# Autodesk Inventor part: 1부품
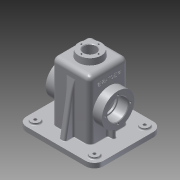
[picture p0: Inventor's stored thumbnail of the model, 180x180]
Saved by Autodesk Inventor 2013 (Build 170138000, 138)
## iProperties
Created: 2016-01
Part Number: 1부품
Material: 알루미늄 6061
Document SubType Name: Modeling
Designer: Administrator
Density: 2.71 g/cm^3
Mass: 808.405 g
Surface Area: 920.161 cm^2
Volume: 298.305 cm^3
Author: Administrator
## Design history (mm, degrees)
sketch "스케치1"
  geometry: L1 (-65, 57.5)-(65, 57.5); L2 (65, 57.5)-(65, -57.5); L3 (65, -57.5)-(-65, -57.5); L4 (-65, -57.5)-(-65, 57.5); L5 (-65, 57.5)-(65, -57.5); L6 (65, 57.5)-(-65, -57.5); 1 further point
  constraints: 12 end point, 2 midpoint, 2 parallel, 1 horizontal, 1 perpendicular
  dimensions: "d0" = 130 distance of L2.end L3.end; "d2" = 115 distance of L1.end L2.end
extrude "돌출1" new body sketch "스케치1" distance "d3" = 10; taper "d4" = 0 deg
fillet "모깎기1" dims "d5" = 15
sketch "스케치2"
  geometry: L1 (-32.5, 32.5)-(32.5, 32.5); L2 (32.5, 32.5)-(32.5, -32.5); L3 (32.5, -32.5)-(-32.5, -32.5); L4 (-32.5, -32.5)-(-32.5, 32.5); L5 (-32.5, 32.5)-(32.5, -32.5); L6 (32.5, 32.5)-(-32.5, -32.5); 1 further point
  constraints: 12 end point, 2 midpoint, 2 parallel, 1 horizontal, 1 perpendicular
  dimensions: "d6" = 65 distance of L1.start L1.end; "d8" = 65 distance of L1.end L2.end
extrude "돌출2" join sketch "스케치2" distance "d9" = 100; taper "d10" = 0 deg
fillet "모깎기2" dims "d11" = 8
sketch "스케치3"
  geometry: L1 (65, -42.5)-(65, 42.5) reference; L2 (50, 57.5)-(-50, 57.5) reference; L3 (-65, 42.5)-(-65, -42.5) reference; L4 (-50, -57.5)-(50, -57.5) reference; L5 (-50, -52.5)-(50, -52.5); L6 (60, -42.5)-(60, 42.5); L7 (50, 52.5)-(-50, 52.5); L8 (-60, 42.5)-(-60, -42.5); L9 (-60, -52.5)-(60, 52.5); L10 (60, -52.5)-(-60, 52.5); A1 r 15 centre (50, -42.5) between (50, -57.5) and (65, -42.5) reference; A2 r 15 centre (50, 42.5) between (65, 42.5) and (50, 57.5) reference; A3 r 15 centre (-50, 42.5) between (-50, 57.5) and (-65, 42.5) reference; A4 r 15 centre (-50, -42.5) between (-65, -42.5) and (-50, -57.5) reference; A5 r 10 centre (-50, -42.5) between (-60, -42.5) and (-50, -52.5); A6 r 10 centre (50, -42.5) between (50, -52.5) and (60, -42.5); A7 r 10 centre (50, 42.5) between (60, 42.5) and (50, 52.5); A8 r 10 centre (-50, 42.5) between (-50, 52.5) and (-60, 42.5); 1 further point
  constraints: 12 end point, 8 point on circle, 8 point on line, 8 tangent, 4 centre point, 3 equal radius, 2 midpoint, 2 parallel, 1 horizontal, 1 perpendicular
  dimensions: "d13" = 120 distance of L9.end L10.end; "d15" = 105 distance of L10.end L9.start; "d16" = 10 radius of A5
extrude "돌출3" cut sketch "스케치3" distance "d17" = 2; taper "d18" = 0 deg
sketch "스케치4"
  geometry: L1 (-24.5, -27.5)-(24.5, -27.5); L2 (27.5, -24.5)-(27.5, 24.5); L3 (24.5, 27.5)-(-24.5, 27.5); L4 (-27.5, 24.5)-(-27.5, -24.5); L5 (-27.5, -27.5)-(27.5, 27.5); L6 (27.5, -27.5)-(-27.5, 27.5); A1 r 3 centre (-24.5, -24.5) between (-27.5, -24.5) and (-24.5, -27.5); A2 r 3 centre (24.5, -24.5) between (24.5, -27.5) and (27.5, -24.5); A3 r 3 centre (24.5, 24.5) between (27.5, 24.5) and (24.5, 27.5); A4 r 3 centre (-24.5, 24.5) between (-24.5, 27.5) and (-27.5, 24.5); 1 further point
  constraints: 12 end point, 8 point on circle, 8 point on line, 8 tangent, 4 centre point, 3 equal radius, 2 midpoint, 2 parallel, 1 horizontal, 1 perpendicular
  dimensions: "d19" = 55 distance of L6.end L5.start; "d21" = 55 distance of L5.end L6.end; "d22" = 3 radius of A1
extrude "돌출4" cut sketch "스케치4" distance "d23" = 105; taper "d24" = 0 deg
fillet "모깎기3" dims "d25" = 3
sketch "스케치5"
  geometry: C1 r 20 at (0, 0); 1 further point
  constraints: 1 centre point, 1 coincident
  dimensions: "d26" = 40 diameter of C1
extrude "돌출5" join sketch "스케치5" distance "d27" = 10; taper "d28" = 0 deg
hole "구멍1" diameter "d31" = 21; stored, may be unused: countersink angle "d35" = 90 deg, drill point angle "d37" = 118 deg; dims "d29" = 10, "d30" = 10, "d32" = 6, "d33" = 4, "d34" = 2, "d36" = 8
sketch "스케치6"
  geometry: C1 r 10.5 at (0, 0) reference; 1 further point
  constraints: 1 vertical alignment
  dimensions: "d38" = 14.5 distance of C1.centre point (0, 14.5)
hole "구멍2" sketch "스케치6" at (0, 14.5) diameter "d39" = 2.459; stored, may be unused: countersink angle "d43" = 90 deg, drill point angle "d45" = 118 deg; dims "d40" = 7, "d41" = 4, "d42" = 2, "d44" = 9
sketch "스케치7"
  geometry: L1 (-52.5, 0)-(-52.5, 2) reference; L2 (-52.5, 2)-(-57.5, 2) reference; L3 (-57.5, 2)-(-57.5, 10) reference; L4 (-57.5, 10)-(-32.5, 10) reference; L5 (-32.5, 10)-(-32.5, 110) reference; L6 (-32.5, 110)-(-20, 110) reference; L7 (-20, 110)-(-20, 120) reference; L8 (-20, 120)-(-15.73, 120) reference; L9 (-15.73, 120)-(-15.73, 111) reference; L10 (-15.73, 111)-(-14.5, 110.261) reference; L11 (-14.5, 110.261)-(-13.271, 111) reference; L12 (-13.271, 111)-(-13.271, 120) reference; L13 (-13.271, 120)-(-10.5, 120) reference; L14 (-10.5, 120)-(-10.5, 105) reference; L15 (-10.5, 105)-(-24.5, 105) reference; L16 (-27.5, 102)-(-27.5, 0) reference; L17 (-27.5, 0)-(-52.5, 0) reference; L18 (32.5, 110)-(32.5, 10) reference; L19 (32.5, 10)-(57.5, 10) reference; L20 (57.5, 10)-(57.5, 2) reference; L21 (57.5, 2)-(52.5, 2) reference; L22 (52.5, 2)-(52.5, 0) reference; L23 (52.5, 0)-(27.5, 0) reference; L24 (27.5, 0)-(27.5, 102) reference; L25 (24.5, 105)-(10.5, 105) reference; L26 (10.5, 105)-(10.5, 120) reference; L27 (10.5, 120)-(13.271, 120) reference; L28 (13.271, 120)-(13.271, 111) reference; L29 (13.271, 111)-(14.5, 110.261) reference; L30 (14.5, 110.261)-(15.73, 111) reference; L31 (15.73, 111)-(15.73, 120) reference; L32 (15.73, 120)-(20, 120) reference; L33 (20, 120)-(20, 110) reference; L34 (20, 110)-(32.5, 110) reference; C1 r 27.5 at (0, 55); A1 r 3 centre (-24.5, 102) between (-24.5, 105) and (-27.5, 102) reference; A2 r 3 centre (24.5, 102) between (27.5, 102) and (24.5, 105) reference; 1 further point
  constraints: 1 centre point, 1 vertical alignment
  dimensions: "d49" = 55 diameter of C1; "d50" = 55 distance of point (0, 0) C1.centre
extrude "돌출6" join sketch "스케치7" stored distance "d51" = 95; taper "d52" = 0 deg
hole "구멍3" diameter "d55" = 30; stored, may be unused: countersink angle "d59" = 90 deg, drill point angle "d61" = 0 deg; dims "d56" = 7, "d57" = 35, "d58" = 17, "d60" = 9, "d62" = 10, "d63" = 10
sketch "스케치8"
  geometry: C1 r 17.5 at (0, 0) reference; 2 further points
  constraints: 1 horizontal alignment
  dimensions: "d64" = 21 distance of C1.centre point (-21, 0)
hole "구멍4" sketch "스케치8" at (-21, 0) diameter "d65" = 3.242; stored, may be unused: countersink angle "d69" = 90 deg, drill point angle "d71" = 118 deg; dims "d66" = 8, "d67" = 42, "d68" = 17, "d70" = 10
sketch "스케치9"
  geometry: L1 (-20, 110)-(-20, 120) reference; L2 (-20, 120)-(-15.73, 120) reference; L3 (-15.73, 120)-(-15.73, 111) reference; L4 (-15.73, 111)-(-14.5, 110.261) reference; L5 (-14.5, 110.261)-(-13.271, 111) reference; L6 (-13.271, 111)-(-13.271, 120) reference; L7 (-13.271, 120)-(-10.5, 120) reference; L8 (-10.5, 120)-(-10.5, 105) reference; L9 (-10.5, 105)-(-24.5, 105) reference; L10 (-27.5, 102)-(-27.5, 82.5) reference; L11 (-27.5, 82.5)-(27.5, 82.5) reference; L12 (27.5, 82.5)-(27.5, 102) reference; L13 (24.5, 105)-(10.5, 105) reference; L14 (10.5, 105)-(10.5, 120) reference; L15 (10.5, 120)-(13.271, 120) reference; L16 (13.271, 120)-(13.271, 111) reference; L17 (13.271, 111)-(14.5, 110.261) reference; L18 (14.5, 110.261)-(15.73, 111) reference; L19 (15.73, 111)-(15.73, 120) reference; L20 (15.73, 120)-(20, 120) reference; L21 (20, 120)-(20, 110) reference; L22 (20, 110)-(32.5, 110) reference; L23 (32.5, 110)-(32.5, 82.5) reference; L24 (32.5, 82.5)-(47.5, 82.5) reference; L25 (47.5, 82.5)-(47.5, 77.621) reference; L26 (47.5, 77.621)-(37.5, 77.621) reference; L27 (37.5, 77.621)-(36.526, 76) reference; L28 (37.5, 74.379)-(47.5, 74.379) reference; L29 (47.5, 74.379)-(47.5, 72.5) reference; L30 (47.5, 72.5)-(30.5, 72.5) reference; L31 (30.5, 72.5)-(30.5, 70) reference; L32 (30.5, 70)-(-30.5, 70) reference; L33 (-30.5, 70)-(-30.5, 72.5) reference; L34 (-30.5, 72.5)-(-47.5, 72.5) reference; L35 (-47.5, 72.5)-(-47.5, 74.379) reference; L36 (-47.5, 74.379)-(-37.5, 74.379) reference; L37 (-37.5, 74.379)-(-36.526, 76) reference; L38 (-37.5, 77.621)-(-47.5, 77.621) reference; L39 (-47.5, 77.621)-(-47.5, 82.5) reference; L40 (-47.5, 82.5)-(-32.5, 82.5) reference; L41 (-32.5, 82.5)-(-32.5, 110) reference; L42 (-32.5, 110)-(-20, 110) reference; L43 (-60, 0)-(-60, 2) reference; L44 (-60, 2)-(-65, 2) reference; L45 (-65, 2)-(-65, 10) reference; L46 (-65, 10)-(-32.5, 10) reference; L47 (-32.5, 10)-(-32.5, 27.5) reference; L48 (-32.5, 27.5)-(-47.5, 27.5) reference; L49 (-47.5, 27.5)-(-47.5, 32.379) reference; L50 (-47.5, 32.379)-(-37.5, 32.379) reference; L51 (-37.5, 32.379)-(-36.526, 34) reference; L52 (-37.5, 35.621)-(-47.5, 35.621) reference; L53 (-47.5, 35.621)-(-47.5, 37.5) reference; L54 (-47.5, 37.5)-(-30.5, 37.5) reference; L55 (-30.5, 37.5)-(-30.5, 40) reference; L56 (-30.5, 40)-(30.5, 40) reference; L57 (30.5, 40)-(30.5, 37.5) reference; L58 (30.5, 37.5)-(47.5, 37.5) reference; L59 (47.5, 37.5)-(47.5, 35.621) reference; L60 (47.5, 35.621)-(37.5, 35.621) reference; L61 (37.5, 35.621)-(36.526, 34) reference; L62 (37.5, 32.379)-(47.5, 32.379) reference; L63 (47.5, 32.379)-(47.5, 27.5) reference; L64 (47.5, 27.5)-(32.5, 27.5) reference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; A1 r 3 centre (-24.5, 102) between (-24.5, 105) and (-27.5, 102) reference; A2 r 3 centre (24.5, 102) between (27.5, 102) and (24.5, 105) reference; 1 further point
  constraints: 4 end point, 4 point on line, 2 perpendicular, 1 parallel
  dimensions: "d75" = 15 distance between parallel lines of L75 L71; "d76" = 15 distance between parallel lines of L76 L73
extrude "돌출7" join sketch "스케치9" stored distance "d77" = 6; taper "d78" = 0 deg
sketch "스케치10"
  geometry: L1 (-52.5, 0)-(-52.5, 2) reference; L2 (-52.5, 2)-(-57.5, 2) reference; L3 (-57.5, 2)-(-57.5, 10) reference; L4 (-57.5, 10)-(-32.5, 10) reference; L5 (-32.5, 10)-(-32.5, 110) reference; L6 (-32.5, 110)-(-20, 110) reference; L7 (-20, 110)-(-20, 120) reference; L8 (-20, 120)-(-15.73, 120) reference; L9 (-15.73, 120)-(-15.73, 111) reference; L10 (-15.73, 111)-(-14.5, 110.261) reference; L11 (-14.5, 110.261)-(-13.271, 111) reference; L12 (-13.271, 111)-(-13.271, 120) reference; L13 (-13.271, 120)-(-10.5, 120) reference; L14 (-10.5, 120)-(-10.5, 105) reference; L15 (-10.5, 105)-(-24.5, 105) reference; L16 (-27.5, 102)-(-27.5, 55) reference; L17 (27.5, 0)-(27.5, 55) reference; L18 (52.5, 0)-(27.5, 0) reference; L19 (52.5, 2)-(52.5, 0) reference; L20 (57.5, 2)-(52.5, 2) reference; L21 (57.5, 10)-(57.5, 2) reference; L22 (32.5, 10)-(57.5, 10) reference; L23 (32.5, 110)-(32.5, 10) reference; L24 (20, 110)-(32.5, 110) reference; L25 (20, 120)-(20, 110) reference; L26 (15.73, 120)-(20, 120) reference; L27 (15.73, 111)-(15.73, 120) reference; L28 (14.5, 110.261)-(15.73, 111) reference; L29 (13.271, 111)-(14.5, 110.261) reference; L30 (13.271, 120)-(13.271, 111) reference; L31 (10.5, 120)-(13.271, 120) reference; L32 (10.5, 105)-(10.5, 120) reference; L33 (24.5, 105)-(10.5, 105) reference; L34 (27.5, 55)-(27.5, 102) reference; L35 (-27.5, 0)-(-52.5, 0) reference; L36 (-27.5, 55)-(-27.5, 0) reference; L37 (-32.5, 95.069)-(-47.5, 10); L38 (32.5, 95.069)-(47.5, 10); C1 r 15 at (0, 55) reference; A1 r 3 centre (-24.5, 102) between (-24.5, 105) and (-27.5, 102) reference; A2 r 27.5 centre (0, 55) between (27.5, 55) and (-27.5, 55) reference; A3 r 3 centre (24.5, 102) between (27.5, 102) and (24.5, 105) reference; A4 r 27.5 centre (0, 55) between (-27.5, 55) and (27.5, 55) reference; 1 further point
  constraints: 4 end point, 4 point on line
  dimensions: "d79" = 10 deg angle of L3 L37; "d80" = 10 distance of L37.end L3.end; "d81" = 10 distance of L21.start L38.end; "d82" = 100 deg angle of L22 L38
extrude "돌출8" join sketch "스케치10" stored distance "d83" = 10; taper "d84" = 0 deg
sketch "스케치11"
  geometry: C1 r 7.5 at (-50, 42.5); C2 r 7.5 at (50, 42.5); C3 r 7.5 at (50, -42.5); C4 r 7.5 at (-50, -42.5); A1 r 15 centre (-50, -42.5) between (-65, -42.5) and (-50, -57.5) reference; A2 r 15 centre (50, -42.5) between (50, -57.5) and (65, -42.5) reference; A3 r 15 centre (50, 42.5) between (65, 42.5) and (50, 57.5) reference; A4 r 15 centre (-50, 42.5) between (-50, 57.5) and (-65, 42.5) reference; 1 further point
  constraints: 4 centre point, 4 coincident
  dimensions: "d85" = 15 diameter of C1; "d86" = 15 diameter of C2; "d87" = 15 diameter of C3; "d88" = 15 diameter of C4
extrude "돌출9" join sketch "스케치11" distance "d89" = 3; taper "d90" = 0 deg
sketch "스케치12"
  geometry: L1 (-82.5, 39.5)-(-92.5, 39.5) reference; L2 (-92.5, 39.5)-(-92.5, 45.5) reference; L3 (-92.5, 45.5)-(-82.5, 45.5) reference; L4 (-82.5, 45.5)-(-82.5, 67) reference; L5 (-74.5, 75)-(-55, 75) reference; L6 (-55, 75)-(-55, 89.471) reference; L7 (-55, 89.471)-(-45, 89.471) reference; L8 (-45, 89.471)-(-45, 75) reference; L9 (-45, 75)-(-25.5, 75) reference; L10 (-17.5, 67)-(-17.5, 45.5) reference; L11 (-17.5, 45.5)-(-7.5, 45.5) reference; L12 (-7.5, 45.5)-(-7.5, 39.5) reference; L13 (-7.5, 39.5)-(-17.5, 39.5) reference; L14 (-17.5, 39.5)-(-17.5, 18) reference; L15 (-25.5, 10)-(-45, 10) reference; L16 (-45, 10)-(-45, -4.471) reference; L17 (-45, -4.471)-(-55, -4.471) reference; L18 (-55, -4.471)-(-55, 10) reference; L19 (-55, 10)-(-74.5, 10) reference; L20 (-82.5, 18)-(-82.5, 39.5) reference; L21 (-25.5, 70)-(-74.5, 70) reference; L22 (-77.5, 67)-(-77.5, 18) reference; L23 (-74.5, 15)-(-25.5, 15) reference; L24 (-22.5, 18)-(-22.5, 67) reference; C1 r 7.5 at (0, 0) reference; C2 r 7.5 at (0, 0) reference; C3 r 7.5 at (-100, 85) reference; C4 r 7.5 at (0, 85) reference; C5 r 7.5 at (-100, 0) reference; A1 r 8 centre (-74.5, 67) between (-74.5, 75) and (-82.5, 67) reference; A2 r 8 centre (-25.5, 67) between (-17.5, 67) and (-25.5, 75) reference; A3 r 8 centre (-25.5, 18) between (-25.5, 10) and (-17.5, 18) reference; A4 r 8 centre (-74.5, 18) between (-82.5, 18) and (-74.5, 10) reference; A5 r 3 centre (-25.5, 67) between (-22.5, 67) and (-25.5, 70) reference; A6 r 3 centre (-74.5, 67) between (-74.5, 70) and (-77.5, 67) reference; A7 r 3 centre (-74.5, 18) between (-77.5, 18) and (-74.5, 15) reference; A8 r 3 centre (-25.5, 18) between (-25.5, 15) and (-22.5, 18) reference; 1 further point
hole "구멍5" sketch "스케치12" at (-100, 0), (-100, 85), (0, 0), (0, 85) diameter "d91" = 5; stored, may be unused: countersink angle "d95" = 90 deg, drill point angle "d97" = 0 deg; dims "d92" = 8, "d93" = 42, "d94" = 17, "d96" = 10
sketch "스케치13"
  geometry: L1 (0, -8)-(100, -8) reference; L2 (-10, 44.5)-(-10, 4.5) reference; 2 further points
  constraints: 1 other
  dimensions: "d98" = 32.5 distance from line of point (17, 24.5) L1; "d99" = 27 distance from line of point (17, 24.5) L2
feature "엠보싱1" sketch "스케치13" dims "d100" = 0.5, "d101" = 0
fillet "모깎기4" dims "d102" = 8
chamfer "모따기1" distance "d103" = 1; stored, may be unused: second distance "d104" = 2, angle "d105" = 45 deg
fillet "모깎기5" dims "d106" = 0.3
fillet "모깎기6" dims "d107" = 3
fillet "모깎기7" dims "d112" = 2
sketch "스케치14"
  geometry: L1 (-27.5, -24.5)-(-27.5, 24.5) reference; L2 (-24.5, 27.5)-(24.5, 27.5) reference; L3 (27.5, 24.5)-(27.5, -24.5) reference; L4 (24.5, -27.5)-(-24.5, -27.5) reference; L5 (24.5, 27.5)-(-24.5, 27.5); L6 (-27.5, 24.5)-(-27.5, -24.5); L7 (-24.5, -27.5)-(24.5, -27.5); L8 (27.5, -24.5)-(27.5, 24.5); A1 r 3 centre (-24.5, -24.5) between (-27.5, -24.5) and (-24.5, -27.5) reference; A2 r 3 centre (-24.5, 24.5) between (-24.5, 27.5) and (-27.5, 24.5) reference; A3 r 3 centre (24.5, 24.5) between (27.5, 24.5) and (24.5, 27.5) reference; A4 r 3 centre (24.5, -24.5) between (24.5, -27.5) and (27.5, -24.5) reference; A5 r 3 centre (-24.5, 24.5) between (-24.5, 27.5) and (-27.5, 24.5); A6 r 3 centre (-24.5, -24.5) between (-27.5, -24.5) and (-24.5, -27.5); A7 r 3 centre (24.5, -24.5) between (24.5, -27.5) and (27.5, -24.5); A8 r 3 centre (24.5, 24.5) between (27.5, 24.5) and (24.5, 27.5); 1 further point
  constraints: 8 end point, 8 point on circle, 4 centre point, 7 other
  dimensions: "d109" = 0 distance between parallel lines of L5 L2
extrude "돌출10" cut sketch "스케치14" distance "d110" = 100; taper "d111" = 0 deg
fillet "모깎기8" dims "d113" = 1
feature "면 기울기1" dims angle "d114" = 5 deg
node "솔리드1"
pattern_circular "원형 패턴1" dims angle "d47" = 360 deg
mirror "대칭1"
pattern_circular "원형 패턴2" dims angle "d73" = 360 deg
mirror "대칭2"
node "절단 모서리 투영1"
node "절단 모서리 투영2"
node "절단 모서리 투영3"
node "절단 모서리 투영4"
